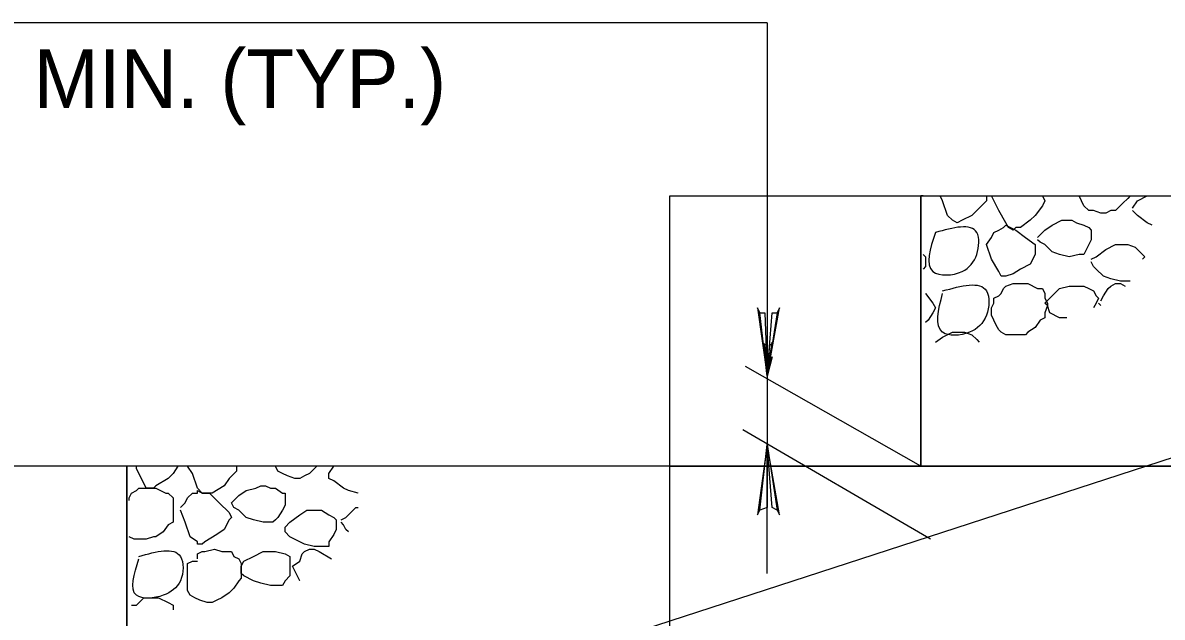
# Model space of a CAD drawing. Extents: x 593 to 1473, y 721 to 1315.
# Drawn here: x 906.2 to 964.7, y 1026.5 to 1057 of the extents above; entities that cross this region are included whole.
import ezdxf

# ---------------------------------------------------------------- set-up
doc = ezdxf.new("R2010")
doc.units = 0
doc.layers.add('2', color=7, linetype='Continuous')

msp = doc.modelspace()

# ---------------------------------------------------------------- linework, layer by layer
at = {"layer": '2'}
for p, q in [((944.445, 1056.975), (904.604, 1056.975)), ((944.445, 1056.975), (944.445, 1035.335)), ((952.32, 1034.21), (943.32, 1039.335)), ((952.82, 1030.46), (943.195, 1036.085)), ((892.32, 1010.96), (967.695, 1035.46)), ((944.445, 1028.71), (944.445, 1035.335))]:
    msp.add_line(p, q, dxfattribs=at)
for points in [[(952.32, 1048.085), (952.32, 1034.21), (939.445, 1034.21), (939.445, 1048.085)], [(904.945, 1034.21), (904.945, 1020.21), (911.57, 1020.21), (911.57, 1034.21)], [(911.57, 1034.21), (911.57, 1020.21), (939.445, 1020.21), (939.445, 1034.21)]]:
    msp.add_lwpolyline(points, close=True, dxfattribs=at)
for points in [[(967.695, 1034.21), (952.32, 1034.21), (952.32, 1048.085), (967.82, 1048.085)], [(952.445, 1048.085), (952.32, 1048.085)], [(953.445, 1047.835), (953.32, 1048.085)], [(955.695, 1048.085), (955.695, 1047.835)], [(956.32, 1047.335), (955.945, 1048.085)], [(958.57, 1048.085), (958.57, 1048.085)], [(958.57, 1048.085), (958.695, 1047.835)], [(960.57, 1047.835), (960.445, 1048.085)], [(963.07, 1048.085), (962.945, 1047.96)], [(963.445, 1047.835), (963.945, 1048.085)], [(953.695, 1047.085), (953.445, 1047.835)], [(955.32, 1047.46), (954.945, 1047.085)], [(955.695, 1047.835), (955.32, 1047.46)], [(958.57, 1047.585), (958.195, 1047.085)], [(958.695, 1047.835), (958.57, 1047.585)], [(960.695, 1047.585), (960.57, 1047.835)], [(960.945, 1047.335), (960.695, 1047.585)], [(962.695, 1047.71), (962.32, 1047.335)], [(962.945, 1047.96), (962.695, 1047.71)], [(963.195, 1047.46), (963.445, 1047.835)], [(953.945, 1046.835), (953.695, 1047.085)], [(954.195, 1046.71), (953.945, 1046.835)], [(954.445, 1046.835), (954.195, 1046.71)], [(954.945, 1047.085), (954.445, 1046.835)], [(956.695, 1046.71), (956.32, 1047.335)], [(957.945, 1046.835), (957.445, 1046.46)], [(958.195, 1047.085), (957.945, 1046.835)], [(959.07, 1046.585), (959.57, 1046.835)], [(959.57, 1046.835), (959.695, 1046.835)], [(959.695, 1046.835), (960.07, 1046.835)], [(960.07, 1046.835), (960.32, 1046.71)], [(961.195, 1047.335), (960.945, 1047.335)], [(961.57, 1047.21), (961.195, 1047.335)], [(961.82, 1047.21), (961.57, 1047.21)], [(962.07, 1047.335), (961.82, 1047.21)], [(962.32, 1047.335), (962.07, 1047.335)], [(963.32, 1047.21), (963.195, 1047.335)], [(963.445, 1047.085), (963.32, 1047.21)], [(963.945, 1046.71), (963.445, 1047.085)], [(954.195, 1046.71), (954.195, 1046.71)], [(956.07, 1046.21), (956.32, 1046.335)], [(956.32, 1046.335), (956.57, 1046.46)], [(956.57, 1046.46), (956.695, 1046.585)], [(956.82, 1046.46), (956.695, 1046.71)], [(956.695, 1046.585), (956.695, 1046.585)], [(956.695, 1046.585), (957.195, 1046.335)], [(957.07, 1046.335), (956.82, 1046.46)], [(957.195, 1046.46), (957.07, 1046.335)], [(957.445, 1046.46), (957.195, 1046.46)], [(957.195, 1046.335), (957.695, 1045.96)], [(958.32, 1045.96), (958.695, 1046.335)], [(958.695, 1046.335), (959.07, 1046.585)], [(960.32, 1046.71), (960.695, 1046.585)], [(960.695, 1046.585), (960.945, 1046.46)], [(960.945, 1046.46), (961.07, 1046.335)], [(961.07, 1046.335), (961.07, 1046.21)], [(964.195, 1046.585), (963.945, 1046.71)], [(955.695, 1045.585), (955.945, 1045.96)], [(955.945, 1045.96), (956.07, 1046.21)], [(957.695, 1045.96), (958.195, 1045.585)], [(958.445, 1045.71), (958.32, 1045.835)], [(958.695, 1045.585), (958.445, 1045.71)], [(961.07, 1045.835), (960.945, 1045.585)], [(961.07, 1046.21), (961.07, 1045.835)], [(952.445, 1045.085), (952.57, 1044.96)], [(955.945, 1044.835), (955.695, 1045.585)], [(958.195, 1045.085), (957.945, 1044.585)], [(958.195, 1045.585), (958.195, 1045.21)], [(958.195, 1045.21), (958.195, 1045.085)], [(959.07, 1045.21), (958.695, 1045.585)], [(959.445, 1045.085), (959.07, 1045.21)], [(959.945, 1044.96), (959.445, 1045.085)], [(960.445, 1045.085), (959.945, 1044.96)], [(960.57, 1045.085), (960.445, 1045.085)], [(960.695, 1045.085), (960.57, 1045.085)], [(960.945, 1045.585), (960.695, 1045.085)], [(961.32, 1044.96), (961.82, 1045.335)], [(961.82, 1045.335), (962.32, 1045.585)], [(962.32, 1045.585), (962.445, 1045.585)], [(962.445, 1045.585), (962.695, 1045.585)], [(962.695, 1045.585), (962.945, 1045.585)], [(962.945, 1045.585), (963.32, 1045.46)], [(963.32, 1045.46), (963.57, 1045.21)], [(963.57, 1045.21), (963.695, 1045.085)], [(963.695, 1045.085), (963.82, 1044.96)], [(952.57, 1044.96), (952.57, 1044.835)], [(952.57, 1044.835), (952.57, 1044.46)], [(956.32, 1044.21), (955.945, 1044.835)], [(957.945, 1044.585), (957.445, 1044.335)], [(961.07, 1044.835), (961.32, 1044.96)], [(961.195, 1044.46), (961.07, 1044.71)], [(963.82, 1044.96), (963.695, 1044.835)], [(952.57, 1044.46), (952.445, 1044.335)], [(956.445, 1043.96), (956.32, 1044.21)], [(956.695, 1043.96), (956.445, 1043.96)], [(957.07, 1044.085), (956.695, 1043.96)], [(956.695, 1043.96), (956.695, 1043.96)], [(957.445, 1044.335), (957.07, 1044.085)], [(961.32, 1044.335), (961.195, 1044.46)], [(961.695, 1043.96), (961.32, 1044.335)], [(962.07, 1043.835), (961.695, 1043.96)], [(956.445, 1043.085), (956.57, 1043.335)], [(956.57, 1043.335), (956.695, 1043.46)], [(956.695, 1043.46), (957.07, 1043.585)], [(957.07, 1043.585), (957.445, 1043.585)], [(957.445, 1043.585), (957.82, 1043.585)], [(957.82, 1043.585), (958.32, 1043.335)], [(958.32, 1043.335), (958.57, 1043.335)], [(958.57, 1043.335), (958.695, 1043.085)], [(958.945, 1042.835), (959.445, 1043.335)], [(959.445, 1043.335), (959.945, 1043.46)], [(959.945, 1043.46), (960.195, 1043.46)], [(960.195, 1043.46), (960.445, 1043.46)], [(960.445, 1043.46), (960.695, 1043.46)], [(960.695, 1043.46), (960.945, 1043.335)], [(960.945, 1043.335), (961.195, 1043.21)], [(961.695, 1042.96), (961.945, 1043.335)], [(961.945, 1043.335), (962.07, 1043.46)], [(962.57, 1043.71), (962.07, 1043.835)], [(962.07, 1043.46), (962.32, 1043.585)], [(962.32, 1043.585), (962.445, 1043.585)], [(962.445, 1043.585), (962.57, 1043.585)], [(963.07, 1043.71), (962.57, 1043.71)], [(962.57, 1043.585), (962.82, 1043.46)], [(952.57, 1043.085), (952.57, 1043.085)], [(952.57, 1043.085), (952.945, 1042.585)], [(956.07, 1042.835), (956.32, 1042.96)], [(956.07, 1042.585), (956.07, 1042.835)], [(956.32, 1042.96), (956.445, 1043.085)], [(958.695, 1043.085), (958.695, 1042.835)], [(958.695, 1042.835), (958.82, 1042.585)], [(958.695, 1042.585), (958.945, 1042.835)], [(961.195, 1043.21), (961.32, 1042.96)], [(961.32, 1042.96), (961.445, 1042.835)], [(961.445, 1042.835), (961.32, 1042.585)], [(961.57, 1042.71), (961.695, 1042.96)], [(944.07, 1042.085), (944.32, 1042.085), (944.445, 1038.835), (944.07, 1042.085), (943.945, 1042.335), (944.445, 1038.835), (944.695, 1042.085), (944.945, 1042.085), (944.445, 1038.835), (945.07, 1042.335), (944.945, 1042.085)], [(952.945, 1042.585), (953.07, 1042.335)], [(953.07, 1042.335), (952.945, 1042.085)], [(955.945, 1042.335), (956.07, 1042.585)], [(955.945, 1041.96), (955.945, 1042.335)], [(958.82, 1042.46), (958.695, 1042.585)], [(958.82, 1042.46), (958.695, 1042.085)], [(958.82, 1042.585), (958.82, 1042.46)], [(958.945, 1042.085), (958.82, 1042.46)], [(961.32, 1042.585), (961.195, 1042.335)], [(961.57, 1042.46), (961.445, 1042.585)], [(952.695, 1041.71), (952.57, 1041.585)], [(952.945, 1042.085), (952.695, 1041.71)], [(956.195, 1041.46), (955.945, 1041.96)], [(958.445, 1041.71), (958.195, 1041.335)], [(958.695, 1041.835), (958.445, 1041.71)], [(958.695, 1042.085), (958.695, 1041.835)], [(959.445, 1041.835), (958.945, 1042.085)], [(959.695, 1041.835), (959.445, 1041.835)], [(959.82, 1041.835), (959.695, 1041.835)], [(953.445, 1040.835), (953.945, 1041.085)], [(953.945, 1041.085), (954.07, 1041.085)], [(954.07, 1041.085), (954.445, 1041.085)], [(954.445, 1041.085), (954.57, 1041.085)], [(954.57, 1041.085), (954.945, 1040.96)], [(954.945, 1040.96), (955.195, 1040.71)], [(956.32, 1041.21), (956.195, 1041.46)], [(956.445, 1041.085), (956.32, 1041.21)], [(956.695, 1040.96), (956.445, 1041.085)], [(957.195, 1040.96), (956.695, 1040.96)], [(957.32, 1040.96), (957.195, 1040.96)], [(957.695, 1040.96), (957.32, 1040.96)], [(957.82, 1041.085), (957.695, 1040.96)], [(958.195, 1041.335), (957.82, 1041.085)], [(944.32, 1040.46), (944.445, 1040.46), (944.445, 1038.835), (944.32, 1040.46), (944.195, 1040.585), (944.445, 1038.835), (944.57, 1040.46), (944.695, 1040.46), (944.445, 1038.835), (944.695, 1040.585), (944.695, 1040.46)], [(953.07, 1040.585), (953.445, 1040.835)], [(955.195, 1040.71), (955.32, 1040.585)], [(944.445, 1039.835), (944.445, 1039.71), (944.445, 1038.835), (944.445, 1039.835), (944.445, 1039.835), (944.445, 1038.835), (944.57, 1039.71), (944.695, 1039.835), (944.445, 1038.835), (944.695, 1039.835), (944.695, 1039.835)], [(944.945, 1031.96), (944.695, 1032.085), (944.445, 1035.335), (944.945, 1031.96), (945.07, 1031.71), (944.445, 1035.335), (944.445, 1032.085), (944.07, 1031.96), (944.445, 1035.335), (943.945, 1031.71), (944.07, 1031.96)], [(912.07, 1034.085), (912.07, 1034.21)], [(912.32, 1033.585), (912.07, 1034.085)], [(914.195, 1034.21), (913.945, 1033.835)], [(914.945, 1033.835), (914.695, 1034.21)], [(917.195, 1033.96), (916.82, 1033.585)], [(917.195, 1034.21), (917.195, 1033.96)], [(919.32, 1033.96), (919.195, 1034.21)], [(919.57, 1033.835), (919.32, 1033.96)], [(921.195, 1034.085), (920.945, 1033.835)], [(921.32, 1034.21), (921.195, 1034.085)], [(921.945, 1033.835), (922.195, 1034.21)], [(967.57, 1020.21), (939.445, 1020.21), (939.445, 1034.21), (967.195, 1034.21), (967.195, 1034.21)], [(912.57, 1033.085), (912.32, 1033.585)], [(913.695, 1033.585), (913.07, 1033.21)], [(913.945, 1033.835), (913.695, 1033.585)], [(915.195, 1033.085), (914.945, 1033.835)], [(916.82, 1033.585), (916.57, 1033.21)], [(919.82, 1033.71), (919.57, 1033.835)], [(920.195, 1033.585), (919.82, 1033.71)], [(920.445, 1033.585), (920.195, 1033.585)], [(920.695, 1033.71), (920.445, 1033.585)], [(920.945, 1033.835), (920.695, 1033.71)], [(921.945, 1033.585), (921.945, 1033.835)], [(922.195, 1033.46), (921.945, 1033.585)], [(922.695, 1033.085), (922.195, 1033.46)], [(911.695, 1032.585), (911.82, 1032.835)], [(911.82, 1032.835), (912.07, 1032.96)], [(912.07, 1032.96), (912.195, 1033.085)], [(912.195, 1033.085), (912.695, 1033.085)], [(912.695, 1033.085), (912.57, 1033.085)], [(912.695, 1033.085), (913.07, 1033.085)], [(912.945, 1033.085), (912.695, 1033.085)], [(913.07, 1033.21), (912.945, 1033.085)], [(913.07, 1033.085), (913.57, 1032.835)], [(913.57, 1032.835), (913.695, 1032.835)], [(913.695, 1032.835), (913.945, 1032.585)], [(914.695, 1032.585), (914.945, 1032.835)], [(914.945, 1032.835), (915.195, 1032.835)], [(915.445, 1032.835), (915.195, 1033.085)], [(915.195, 1032.835), (915.195, 1032.96)], [(915.195, 1032.96), (915.445, 1032.835)], [(915.445, 1032.835), (915.82, 1032.835)], [(915.57, 1032.835), (915.445, 1032.835)], [(915.82, 1032.835), (915.57, 1032.835)], [(915.82, 1032.835), (916.32, 1032.335)], [(915.945, 1032.835), (915.82, 1032.835)], [(916.57, 1033.21), (915.945, 1032.835)], [(917.32, 1032.71), (917.695, 1032.96)], [(917.695, 1032.96), (918.195, 1033.085)], [(918.195, 1033.085), (918.445, 1033.21)], [(918.445, 1033.21), (918.695, 1033.21)], [(918.695, 1033.21), (918.945, 1033.085)], [(918.945, 1033.085), (919.195, 1033.085)], [(919.195, 1033.085), (919.57, 1032.835)], [(919.57, 1032.835), (919.695, 1032.835)], [(919.695, 1032.835), (919.695, 1032.585)], [(922.945, 1032.96), (922.695, 1033.085)], [(923.445, 1032.835), (922.945, 1032.96)], [(923.445, 1032.835), (923.445, 1032.835)], [(911.695, 1032.46), (911.695, 1032.585)], [(913.945, 1032.585), (913.945, 1032.335)], [(913.945, 1032.335), (913.945, 1032.085)], [(914.32, 1032.085), (914.57, 1032.335)], [(914.57, 1032.335), (914.695, 1032.585)], [(916.32, 1032.335), (916.82, 1031.835)], [(916.945, 1032.335), (917.32, 1032.71)], [(917.07, 1032.085), (916.945, 1032.335)], [(919.695, 1032.21), (919.57, 1031.96)], [(919.695, 1032.585), (919.695, 1032.21)], [(913.945, 1032.085), (913.945, 1031.96)], [(913.945, 1031.96), (913.945, 1031.585)], [(914.57, 1031.335), (914.32, 1031.96)], [(916.82, 1031.835), (916.945, 1031.585)], [(917.32, 1031.96), (917.07, 1032.085)], [(917.695, 1031.585), (917.32, 1031.96)], [(919.57, 1031.96), (919.32, 1031.585)], [(919.945, 1031.335), (920.445, 1031.71)], [(920.445, 1031.71), (920.82, 1031.96)], [(920.82, 1031.96), (921.07, 1031.96)], [(921.07, 1031.96), (921.32, 1031.96)], [(921.32, 1031.96), (921.57, 1031.96)], [(921.57, 1031.96), (921.945, 1031.71)], [(921.945, 1031.71), (922.195, 1031.585)], [(922.82, 1031.585), (923.32, 1032.085)], [(923.32, 1032.085), (923.445, 1032.085)], [(913.695, 1031.21), (913.445, 1030.835)], [(913.945, 1031.335), (913.695, 1031.21)], [(913.945, 1031.585), (913.945, 1031.335)], [(914.82, 1030.585), (914.57, 1031.335)], [(916.82, 1031.46), (916.57, 1030.96)], [(916.945, 1031.585), (916.82, 1031.46)], [(918.07, 1031.46), (917.695, 1031.585)], [(918.57, 1031.335), (918.07, 1031.46)], [(919.07, 1031.335), (918.57, 1031.335)], [(919.195, 1031.46), (919.07, 1031.335)], [(919.32, 1031.585), (919.195, 1031.46)], [(919.695, 1031.085), (919.945, 1031.335)], [(919.695, 1030.835), (919.695, 1031.085)], [(922.195, 1031.585), (922.32, 1031.46)], [(922.32, 1031.46), (922.32, 1031.335)], [(922.32, 1031.335), (922.32, 1030.96)], [(922.57, 1031.46), (922.82, 1031.585)], [(922.695, 1031.21), (922.57, 1031.335)], [(922.82, 1030.96), (922.695, 1031.21)], [(911.945, 1030.46), (911.695, 1030.585)], [(912.32, 1030.46), (911.945, 1030.46)], [(912.57, 1030.46), (912.32, 1030.46)], [(912.945, 1030.585), (912.57, 1030.46)], [(913.07, 1030.585), (912.945, 1030.585)], [(913.445, 1030.835), (913.07, 1030.585)], [(915.195, 1030.335), (914.82, 1030.585)], [(916.195, 1030.71), (915.57, 1030.335)], [(916.57, 1030.96), (916.195, 1030.71)], [(919.945, 1030.585), (919.695, 1030.835)], [(920.445, 1030.335), (919.945, 1030.585)], [(922.195, 1030.71), (921.945, 1030.335)], [(922.32, 1030.96), (922.195, 1030.71)], [(922.945, 1030.835), (922.82, 1030.96)], [(915.195, 1030.21), (915.195, 1030.335)], [(915.445, 1030.21), (915.195, 1030.21)], [(915.57, 1030.335), (915.445, 1030.21)], [(915.57, 1029.835), (916.07, 1029.96)], [(916.07, 1029.96), (916.445, 1029.835)], [(920.695, 1030.21), (920.445, 1030.335)], [(921.195, 1030.085), (920.695, 1030.21)], [(920.695, 1029.835), (920.945, 1029.96)], [(920.945, 1029.96), (921.07, 1029.96)], [(921.07, 1029.96), (921.195, 1029.96)], [(921.82, 1030.085), (921.195, 1030.085)], [(921.195, 1029.96), (921.445, 1029.835)], [(921.945, 1030.085), (921.82, 1030.085)], [(921.945, 1030.335), (921.945, 1030.085)], [(914.695, 1029.21), (914.945, 1029.335)], [(914.945, 1029.335), (915.195, 1029.335)], [(915.195, 1029.71), (915.445, 1029.835)], [(915.195, 1029.46), (915.195, 1029.71)], [(915.445, 1029.835), (915.57, 1029.835)], [(916.445, 1029.835), (916.945, 1029.835)], [(916.945, 1029.835), (917.07, 1029.585)], [(917.07, 1029.585), (917.32, 1029.46)], [(917.32, 1029.46), (917.445, 1029.21)], [(917.445, 1029.085), (917.57, 1029.335)], [(917.57, 1029.335), (918.07, 1029.585)], [(918.07, 1029.585), (918.57, 1029.835)], [(918.57, 1029.835), (918.695, 1029.835)], [(918.695, 1029.835), (919.07, 1029.835)], [(919.07, 1029.835), (919.195, 1029.835)], [(919.195, 1029.835), (919.695, 1029.71)], [(919.695, 1029.71), (919.945, 1029.585)], [(919.945, 1029.585), (919.945, 1029.335)], [(919.945, 1029.335), (919.945, 1029.21)], [(920.07, 1029.085), (920.445, 1029.335)], [(920.445, 1029.335), (920.57, 1029.71)], [(920.57, 1029.71), (920.695, 1029.835)], [(921.445, 1029.835), (922.07, 1029.46)], [(914.695, 1029.085), (914.695, 1029.21)], [(914.695, 1028.71), (914.695, 1029.085)], [(914.695, 1028.335), (914.695, 1028.71)], [(917.445, 1029.21), (917.445, 1028.96)], [(917.445, 1028.71), (917.445, 1029.085)], [(917.445, 1028.96), (917.445, 1028.71)], [(917.445, 1028.71), (917.445, 1028.46)], [(917.57, 1028.585), (917.445, 1028.71)], [(919.945, 1029.21), (919.945, 1028.96)], [(919.945, 1028.96), (919.945, 1028.585)], [(920.445, 1028.335), (920.07, 1029.085)], [(914.695, 1027.835), (914.695, 1028.335)], [(917.32, 1028.335), (917.07, 1027.96)], [(917.445, 1028.46), (917.32, 1028.335)], [(918.07, 1028.335), (917.57, 1028.585)], [(918.445, 1028.21), (918.07, 1028.335)], [(918.945, 1028.085), (918.445, 1028.21)], [(919.695, 1028.335), (919.57, 1028.085)], [(919.945, 1028.585), (919.695, 1028.335)], [(920.445, 1028.335), (920.445, 1028.335)], [(914.82, 1027.585), (914.695, 1027.835)], [(915.07, 1027.46), (914.82, 1027.585)], [(916.82, 1027.71), (916.445, 1027.46)], [(917.07, 1027.96), (916.82, 1027.71)], [(919.445, 1028.085), (918.945, 1028.085)], [(919.57, 1028.085), (919.445, 1028.085)], [(911.82, 1027.085), (912.07, 1027.085)], [(912.07, 1027.085), (912.445, 1027.46)], [(912.445, 1027.46), (912.695, 1027.46)], [(912.695, 1027.46), (912.945, 1027.46)], [(912.945, 1027.46), (913.195, 1027.46)], [(913.195, 1027.46), (913.695, 1027.21)], [(913.695, 1027.21), (913.945, 1027.085)], [(913.945, 1027.085), (913.945, 1026.96)], [(913.945, 1026.96), (913.945, 1026.835)], [(915.32, 1027.335), (915.07, 1027.46)], [(915.695, 1027.21), (915.32, 1027.335)], [(915.945, 1027.21), (915.695, 1027.21)], [(916.195, 1027.335), (915.945, 1027.21)], [(916.445, 1027.46), (916.195, 1027.335)], [(913.945, 1026.835), (913.945, 1026.835)]]:
    msp.add_lwpolyline(points, dxfattribs=at)
for points in [[(953.07, 1046.21), (955.195, 1046.21), (955.195, 1045.085), (954.445, 1044.21), (952.945, 1044.21), (953.07, 1046.21)], [(953.445, 1043.21), (955.695, 1043.21), (955.695, 1041.96), (954.82, 1041.085), (953.445, 1041.085), (953.445, 1043.085)], [(912.195, 1029.585), (914.32, 1029.585), (914.32, 1028.335), (913.445, 1027.585), (912.07, 1027.585), (912.195, 1029.46)]]:
    msp.add_spline(points, degree=3, dxfattribs=at)

# ---------------------------------------------------------------- texts
msp.add_text('MIN. (TYP.)', height=3, dxfattribs=at).set_placement((906.791, 1052.607))

doc.saveas('drawing.dxf')
